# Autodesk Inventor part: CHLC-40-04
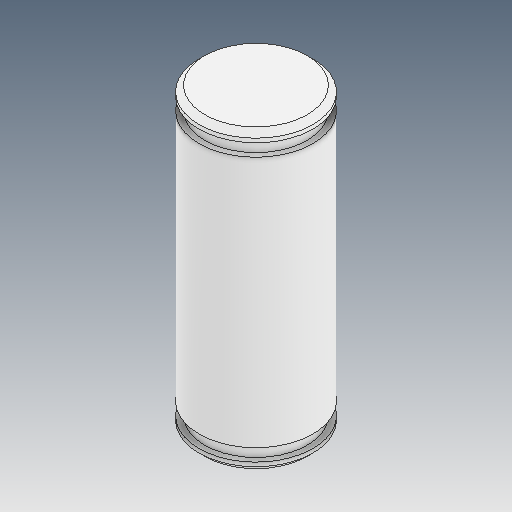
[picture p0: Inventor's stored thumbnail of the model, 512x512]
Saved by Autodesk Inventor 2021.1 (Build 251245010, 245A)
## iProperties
Created: 2021-05
Part Number: CHLC-40-04
Material: Ogólny
Document SubType Name: Modeling
Designer: user
Density: 1 g/cm^3
Appearance: Domyślna
Author: user
Revision Number: ÈÎºÎ
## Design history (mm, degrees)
feature "ÊäÈë1"
node "Bryła1"
